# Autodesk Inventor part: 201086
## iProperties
Created: 2007-10
Part Number: 201086
Document SubType Name: Modeling
Designer: TH
Density: 7.85 g/cm^3
Mass: 50.414 g
Surface Area: 38.0293 cm^2
Volume: 6.42217 cm^3
Material: Steel
Description: PIVOT PLATE
Component Category: Lower Component
Author: TH
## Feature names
1. Extrusion1
2. Hole1
3. Hole2
